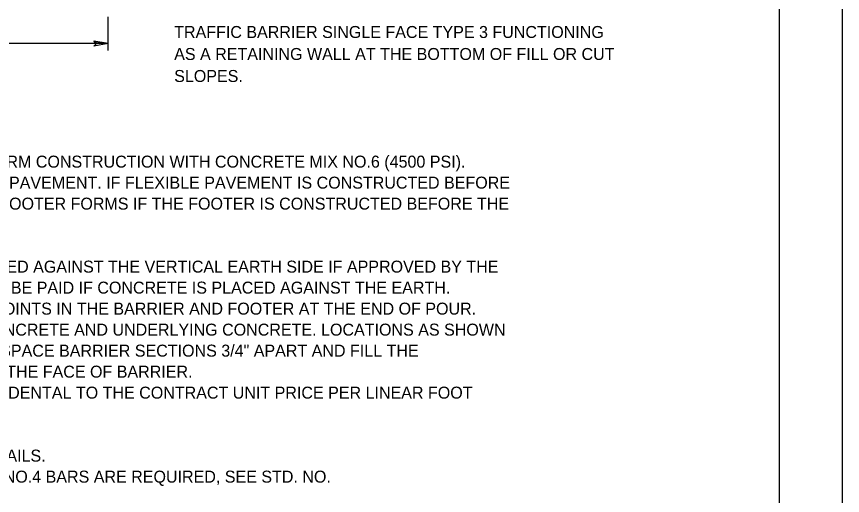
# Model space of a CAD drawing. Extents: x -27.4 to -18.9, y -4.2 to 6.8.
# Drawn here: x -23.046 to -18.916, y -1.823 to 0.571 of the extents above; entities that cross this region are included whole.
import ezdxf

# ---------------------------------------------------------------- set-up
doc = ezdxf.new("R2010")
doc.units = 0
for name, color, linetype in [('BORD-LINE', 7, 'Continuous'), ('DETL-DIMS', 7, 'Continuous'), ('Level 10', 7, 'Continuous'), ('Level 12', 7, 'Continuous'), ('Level 13', 7, 'Continuous'), ('USER-CLIP', 7, 'Continuous')]:
    doc.layers.add(name, color=color, linetype=linetype)

msp = doc.modelspace()

# ---------------------------------------------------------------- linework, layer by layer
at = {"layer": 'BORD-LINE'}
msp.add_lwpolyline([(-26.6066, 6.4791), (-19.2324, 6.4791), (-19.2324, -3.874), (-26.6066, -3.874)], close=True, dxfattribs=at)
at = {"layer": 'DETL-DIMS'}
for p, q in [((-22.588, 0.4358), (-22.6595, 0.4232)), ((-22.646, 0.4358), (-22.6595, 0.4232)), ((-22.588, 0.4358), (-22.6594, 0.4484)), ((-22.6594, 0.4484), (-22.646, 0.4358))]:
    msp.add_line(p, q, dxfattribs=at)
msp.add_lwpolyline([(-22.6594, 0.4484), (-22.588, 0.4358), (-22.6595, 0.4232), (-22.646, 0.4358)], close=True, dxfattribs=at)
at = {"layer": 'Level 10'}
for p, q in [((-22.588, 0.4014), (-22.588, 0.5695)), ((-22.588, 0.4358), (-24.9207, 0.4358))]:
    msp.add_line(p, q, dxfattribs=at)
at = {"layer": 'USER-CLIP'}
msp.add_lwpolyline([(-18.9155, 6.8091), (-27.4155, 6.8091), (-27.4155, -4.1909), (-18.9155, -4.1909)], close=True, dxfattribs=at)

# ---------------------------------------------------------------- texts
at = {"layer": 'Level 12'}
for s, p in [('TRAFFIC BARRIER SINGLE FACE TYPE 3 FUNCTIONING ', (-22.2579, 0.4639)), ('AS A RETAINING WALL AT THE BOTTOM OF FILL OR CUT ', (-22.2579, 0.3539)), ('SLOPES.', (-22.2579, 0.2439))]:
    msp.add_text(s, height=0.06, dxfattribs=at).set_placement(p)
at = {"layer": 'Level 13'}
for s, p in [('CAST THE BARRIER AND FOOTER SEPARATELY USING FIXED FORM OR SLIP FORM CONSTRUCTION WITH CONCRETE MIX NO.6 (4500 PSI).', (-26.2354, -0.1843)), ('THE BARRIER FOOTER MAY BE CONSTRUCTED AFTER CONSTRUCTION OF THE PAVEMENT. IF FLEXIBLE PAVEMENT IS CONSTRUCTED BEFORE ', (-26.2354, -0.2893)), ('THE FOOTER, SAWCUT THE PAVEMENT TO PROVIDE A CLEAN EDGE. REMOVE FOOTER FORMS IF THE FOOTER IS CONSTRUCTED BEFORE THE', (-26.2354, -0.3943)), ('THE FOOTER REAR VERTICAL FACE MAY BE FORMED OR THE CONCRETE PLACED AGAINST THE VERTICAL EARTH SIDE IF APPROVED BY THE ', (-26.2354, -0.7093)), ('ENGINEER. NO ADDITIONAL COMPENSATION FOR ADDITIONAL CONCRETE WILL BE PAID IF CONCRETE IS PLACED AGAINST THE EARTH. ', (-26.2354, -0.8143)), ('MAXIMUM SPACING OF CONTRACTION JOINTS IS 20 FEET. PLACE EXPANSION JOINTS IN THE BARRIER AND FOOTER AT THE END OF POUR.', (-26.2354, -0.9193)), ('AT PC AND PT LOCATIONS, STRUCTURES, EXPANSION JOINTS IN ABUTTING CONCRETE AND UNDERLYING CONCRETE. LOCATIONS AS SHOWN', (-26.2354, -1.0243)), ('ON THE PLANS, AND AS DIRECTED BY THE ENGINEER. AT EXPANSION JOINTS, SPACE BARRIER SECTIONS 3/4" APART AND FILL THE ', (-26.2354, -1.1293)), ('OPENING WITH 3/4" PREFORMED JOINT FILLER. RECESS THE FILLER 1/4" FROM THE FACE OF BARRIER.', (-26.2354, -1.2343)), ('COST OF THE CONCRETE FOOTER, REINFORCEMENT, AND EXCAVATION IS INCIDENTAL TO THE CONTRACT UNIT PRICE PER LINEAR FOOT ', (-26.2354, -1.3393)), ('CONDUIT: IF REQUIRED REFER TO STD. NO. MD 648.50 FOR LOCATION AND DETAILS.', (-26.2354, -1.6543)), ('WHEN BARRIER IS CONSTRUCTED USING THE SLIP FORM METHOD, DIAGONAL NO.4 BARS ARE REQUIRED, SEE STD. NO. ', (-26.2354, -1.7593))]:
    msp.add_text(s, height=0.06, dxfattribs=at).set_placement(p)

doc.saveas('drawing.dxf')
